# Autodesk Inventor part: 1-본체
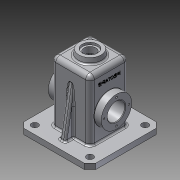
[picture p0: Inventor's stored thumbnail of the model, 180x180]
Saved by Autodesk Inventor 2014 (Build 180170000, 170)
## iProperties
Created: 2016-02
Part Number: 1-본체
Material: 알루미늄 6061
Document SubType Name: Modeling
Designer: Administrator
Density: 2.71 g/cm^3
Appearance: 알루미늄 - 평지
Mass: 938.855 g
Surface Area: 1044.32 cm^2
Volume: 346.441 cm^3
Author: Administrator
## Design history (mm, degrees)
node "작업 평면1"
sketch "스케치1"
  geometry: L1 (-65, 65)-(65, 65); L2 (65, 65)-(65, -65); L3 (65, -65)-(-65, -65); L4 (-65, -65)-(-65, 65); 3 further points
  constraints: 8 end point, 2 midpoint, 2 parallel, 1 horizontal, 1 horizontal alignment, 1 perpendicular, 1 vertical alignment
  dimensions: "d1" = 130 distance of L1.start L1.end; "d2" = 130 distance of L1.end L2.end
extrude "돌출1" new body sketch "스케치1" distance "d3" = 10; taper "d4" = 0 deg
sketch "스케치2"
  geometry: L1 (-35, 35)-(35, 35); L2 (35, 35)-(35, -35); L3 (35, -35)-(-35, -35); L4 (-35, -35)-(-35, 35); L5 (30, 30)-(-30, 30); L6 (-30, 30)-(-30, -30); L7 (-30, -30)-(30, -30); L8 (30, -30)-(30, 30); 3 further points
  constraints: 16 end point, 4 parallel, 3 perpendicular, 2 midpoint, 1 horizontal, 1 horizontal alignment, 1 vertical alignment, 3 other
  dimensions: "d5" = 70 distance of L1.start L1.end; "d8" = 5 distance between parallel lines of L2 L8
extrude "돌출2" join sketch "스케치2" distance "d6" = 120; taper "d7" = 0 deg
extrude "돌출3" cut sketch "스케치2" distance "d9" = 115; taper "d10" = 0 deg
sketch "스케치3"
  geometry: C1 r 27.5 at (0, 0); 1 further point
  constraints: 1 centre point, 1 coincident
  dimensions: "d11" = 55 diameter of C1
extrude "돌출4" join sketch "스케치3" stored distance "d12" = 96; taper "d13" = 0 deg
hole "구멍1" diameter "d16" = 32; stored, may be unused: countersink angle "d20" = 90 deg, drill point angle "d22" = 118 deg; dims "d14" = 10, "d15" = 10, "d17" = 6, "d18" = 4, "d19" = 2, "d21" = 8
sketch "스케치6" dims "d32" = 45
  geometry: 3 further points
  constraints: 2 horizontal alignment, 1 coincident, 2 other
hole "구멍2" sketch "스케치6" at (-22.5, 0) diameter "d33" = 3.242; stored, may be unused: countersink angle "d37" = 90 deg, drill point angle "d39" = 118 deg; dims "d34" = 8, "d35" = 4, "d36" = 2, "d38" = 10
sketch "스케치4"
  geometry: L1 (30, -55)-(30, 60) reference; L2 (-30, -55)-(-30, 60) reference; L3 (30, 27.5)-(-30, 27.5); L4 (-30, 27.5)-(-23, 20.5); L5 (-23, 20.5)-(-23, 0); L6 (-23, 0)-(23, 0); L7 (23, 0)-(23, 20.5); L8 (23, 20.5)-(30, 27.5); 2 further points
  constraints: 12 end point, 4 perpendicular, 2 point on line, 1 coincident, 1 midpoint
  dimensions: "d23" = 135 deg angle of L1 L8; "d24" = 135 deg angle of L2 L4; "d25" = 7 distance between parallel lines of L7 L1; "d26" = 55 diameter of L3 L6
revolve "회전1" sketch "스케치4" stored, may be unused: angle "d27" = 90 deg
node "작업 평면2"
sketch "스케치5"
  geometry: C1 r 20 at (0, 0); 1 further point
  constraints: 1 centre point, 1 coincident
  dimensions: "d29" = 40 diameter of C1
extrude "돌출5" join sketch "스케치5" stored distance "d30" = 96; taper "d31" = 10 deg
hole "구멍3" diameter "d45" = 21; stored, may be unused: countersink angle "d49" = 90 deg, drill point angle "d51" = 0 deg; dims "d43" = 10, "d44" = 10, "d46" = 8, "d47" = 28, "d48" = 4, "d50" = 10
sketch "스케치7"
  geometry: L1 (35, 65)-(35, -45) reference; L2 (35, -45)-(65, -45) reference; L3 (65, -45)-(65, -55) reference; L4 (65, -55)-(30, -55) reference; L5 (30, -55)-(30, 60) reference; L6 (30, 60)-(10.5, 60) reference; L7 (10.5, 60)-(10.5, 71) reference; L8 (10.5, 71)-(14, 71) reference; L9 (14, 71)-(14, 75) reference; L10 (14, 75)-(20, 75) reference; L11 (20, 75)-(21.763, 65) reference; L12 (21.763, 65)-(35, 65) reference; L13 (-30, -55)-(-65, -55) reference; L14 (-65, -55)-(-65, -45) reference; L15 (-65, -45)-(-35, -45) reference; L16 (-35, -45)-(-35, 65) reference; L17 (-35, 65)-(-21.763, 65) reference; L18 (-21.763, 65)-(-20, 75) reference; L19 (-20, 75)-(-14, 75) reference; L20 (-14, 75)-(-14, 71) reference; L21 (-14, 71)-(-10.5, 71) reference; L22 (-10.5, 71)-(-10.5, 60) reference; L23 (-10.5, 60)-(-30, 60) reference; L24 (-30, 60)-(-30, -55) reference; L25 (-50, -45)-(-35, 40.069); L26 (35, 40.069)-(50, -45); 1 further point
  constraints: 4 end point, 2 midpoint, 2 point on line
  dimensions: "d52" = 15 distance from line of L14 L25.start; "d53" = 10 deg angle of L14 L25; "d54" = 15 distance from line of L3 L26.end (= d52); "d55" = 10 deg angle of L3 L26 (= d53)
  node "절단 모서리 투영1"
feature "리브1" dims "d56" = 1, "d57" = 10, "d58" = 0, "d59" = 0, "d60" = 1, "d61" = 1
feature "리브2" dims "d62" = 1, "d63" = 10, "d64" = 0, "d65" = 0, "d66" = 1, "d67" = 1
chamfer "모따기1" distance "d68" = 10; stored, may be unused: second distance "d69" = 2, angle "d70" = 45 deg
sketch "스케치8"
  geometry: L1 (-50, -50)-(50, -50); L2 (50, -50)-(50, 50); L3 (50, 50)-(-50, 50); L4 (-50, 50)-(-50, -50); 7 further points
  constraints: 8 end point, 4 coincident, 2 midpoint, 2 parallel, 2 perpendicular, 1 horizontal, 1 horizontal alignment, 1 vertical alignment
  dimensions: "d71" = 100 distance of L3.end L1.start
hole "구멍4" sketch "스케치8" at (-50, -50), (50, -50), (50, 50), (-50, 50) diameter "d72" = 12; stored, may be unused: countersink angle "d76" = 90 deg, drill point angle "d78" = 0 deg; dims "d73" = 8, "d74" = 28, "d75" = 4, "d77" = 10
fillet "모깎기1" dims "d79" = 8
fillet "모깎기2" dims "d80" = 8
fillet "모깎기3" dims "d81" = 0.5
chamfer "모따기2" distance "d82" = 1; stored, may be unused: second distance "d83" = 2, angle "d84" = 45 deg
fillet "모깎기4" dims "d85" = 3
fillet "모깎기5" dims "d86" = 3
fillet "모깎기9" dims "d93" = 3
fillet "모깎기10" dims "d94" = 3
fillet "모깎기11" dims "d95" = 3
sketch "스케치9"
  geometry: L1 (6.365, 6.261)-(6.365, 47.739); L2 (6.365, 47.739)-(17.635, 47.739); L3 (17.635, 47.739)-(17.635, 6.261); L4 (17.635, 6.261)-(6.365, 6.261); L5 (-18, 7)-(-18, 47) reference; 3 further points
  constraints: 2 midpoint, 1 horizontal alignment, 2 other
  dimensions: "d90" = 30 distance from line of L5 point (12, 47.739)
feature "엠보싱1" sketch "스케치9" dims "d91" = 0.5, "d92" = 0
node "솔리드1"
pattern_circular "원형 패턴1" dims angle "d41" = 360 deg
mirror "대칭1"
other parameters: "d0" = -55
